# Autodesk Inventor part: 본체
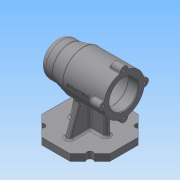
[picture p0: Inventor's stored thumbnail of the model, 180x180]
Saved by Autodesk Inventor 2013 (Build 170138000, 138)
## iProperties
Created: 2021-01
Part Number: 본체
Material: Generic
Document SubType Name: Modeling
Designer: Administrator
Density: 1 g/cm^3
Author: Administrator
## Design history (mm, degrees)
sketch "스케치1" dims "d0" = 100
  geometry: L1 (20.711, 50)-(50, 20.711); L2 (50, 20.711)-(50, -20.711); L3 (50, -20.711)-(20.711, -50); L4 (20.711, -50)-(-20.711, -50); L5 (-20.711, -50)-(-50, -20.711); L6 (-50, -20.711)-(-50, 20.711); L7 (-50, 20.711)-(-20.711, 50); L8 (-20.711, 50)-(20.711, 50); 4 further points
  constraints: 16 end point, 2 coincident, 2 vertical alignment, 1 midpoint, 19 other
extrude "돌출1" new body sketch "스케치1" distance "d2" = 10; taper "d3" = 0 deg
sketch "스케치2"
  geometry: L1 (-50, -10)-(-20.711, -10) reference; L2 (20.711, 0)-(50, 0) reference; L3 (50, 65)-(-50, 65); L4 (-50, 65)-(-50, 90); L5 (-50, 90)-(-30, 90); L6 (-30, 90)-(-10, 95); L7 (-10, 95)-(50, 95); L8 (50, 95)-(50, 86); L9 (50, 86)-(35, 86); L10 (35, 86)-(35, 89); L11 (35, 89)-(-7, 89); L12 (-7, 89)-(-7, 86); L13 (-7, 86)-(-19, 86); L14 (-19, 86)-(-19, 82.5); L15 (-19, 82.5)-(-37, 82.5); L16 (-37, 82.5)-(-37, 81); L17 (-37, 81)-(-41, 81); L18 (-41, 81)-(-41, 75.5); L19 (-41, 75.5)-(-44, 75.5); L20 (-44, 75.5)-(-44, 65); 1 further point
  constraints: 36 end point, 14 parallel, 3 perpendicular, 1 point on line, 1 vertical alignment
  dimensions: "d5" = 75 distance between parallel lines of L3 L1; "d6" = 100 distance of L3.start L3.end; "d8" = 21 diameter of L19 L3; "d9" = 32 diameter of L17 L3; "d10" = 35 diameter of L15 L3; "d11" = 42 diameter of L13 L3; "d12" = 48 diameter of L11 L3; "d13" = 42 diameter of L9 L3; "d14" = 60 diameter of L7 L3; "d15" = 50 diameter of L5 L3; "d16" = 3 distance of L18.end L19.end; "d17" = 4 distance of L16.end L17.end; "d18" = 18 distance of L14.end L15.end; "d19" = 12 distance of L12.end L13.end; "d20" = 42 distance of L10.end L11.end; "d21" = 15 distance of L8.end L9.end; "d22" = 20 distance of L5.end L4.end; "d23" = 40 horizontal distance of L6.end L4.end; "d24" = 100 distance between parallel lines of L8 L4
revolve "회전1" sketch "스케치2" stored, may be unused: angle "d25" = 90 deg
sketch "스케치3"
  geometry: L1 (-20.711, 0)-(20.711, 0) reference; L2 (-50, 0)-(-20.711, 0) reference; L3 (20.711, 0)-(50, 0) reference; L4 (-50, 40)-(-30, 40) reference; L5 (-30, 40)-(-10, 35) reference; L6 (-10, 35)-(50, 35) reference; L7 (-27, 0)-(-19.225, 40); L8 (27, 35)-(27, 0); L9 (-19.225, 40)-(27, 40); L10 (27, 40)-(27, 35); 1 further point
  constraints: 8 end point, 4 point on line, 3 perpendicular
  dimensions: "d26" = 23 distance of L7.start L2.start; "d27" = 101 deg angle of L7 L2; "d28" = 23 distance of L3.end L8.end
extrude "돌출2" join sketch "스케치3" stored distance "d29" = 8; taper "d30" = 0 deg
sketch "스케치4"
  geometry: L1 (-50, 0)-(-20.711, 0) reference; L2 (-20.711, 0)-(-20.711, -10) reference; L3 (-50, -10)-(-20.711, -10) reference; L4 (-50, 0)-(-50, -10) reference; L5 (20.711, 0)-(50, 0) reference; L6 (-35, 0)-(-19.606, 42.293); L7 (19.606, 42.293)-(35, 0); A1 r 30 centre (0, 65) between (4, 35.268) and (-4, 35.268) reference; 1 further point
  constraints: 4 end point, 2 point on circle, 2 point on line
  dimensions: "d31" = 15 distance of L6.start L1.start; "d32" = 15 distance of L5.end L7.end; "d33" = 110 deg angle of L6 L1; "d34" = 110 deg angle of L5 L7
  node "투영된 루프1"
feature "리브1" dims "d35" = 1, "d36" = 8, "d37" = 0, "d38" = 0, "d39" = 1, "d40" = 1
feature "리브2" dims "d41" = 1, "d42" = 8, "d43" = 0, "d44" = 0, "d45" = 1, "d46" = 1
sketch "스케치5"
  geometry: C1 r 21 at (0, 0) reference; C2 r 6 at (0, -30); C3 r 6 at (30, 0); C4 r 6 at (0, 30); C5 r 6 at (-30, 0); A1 r 30 centre (0, 0) between (0, -30) and (30, 0) reference; 1 further point
  constraints: 4 centre point, 4 point on circle, 3 equal radius, 2 horizontal alignment, 2 vertical alignment
  dimensions: "d47" = 12 diameter of C2
extrude "돌출3" join sketch "스케치5" distance "d49" = 16; taper "d50" = 0 deg
sketch "스케치6"
  geometry: A1 r 6 centre (0, 0) between (-5.97, 0.6) and (5.97, 0.6) reference; A2 r 6 centre (30, 30) between (29.4, 24.03) and (29.4, 35.97) reference; A3 r 6 centre (0, 60) between (5.97, 59.4) and (-5.97, 59.4) reference; A4 r 6 centre (-30, 30) between (-29.4, 35.97) and (-29.4, 24.03) reference; 5 further points
  constraints: 4 coincident
hole "구멍1" sketch "스케치6" at (0, 60), (-30, 30), (0, 0), (30, 30) diameter "d51" = 3.242; stored, may be unused: countersink angle "d55" = 90 deg, drill point angle "d57" = 118 deg; dims "d52" = 8, "d53" = 4, "d54" = 2, "d56" = 10
sketch "스케치7"
  geometry: L1 (20.711, 50)-(50, 20.711) reference; L2 (-50, 20.711)-(-20.711, 50) reference; L3 (-20.711, -50)-(-50, -20.711) reference; L4 (50, -20.711)-(20.711, -50) reference; L5 (0, 0)-(-35.355, 35.355); L6 (0, 0)-(-35.355, -35.355); L7 (0, 0)-(35.355, -35.355); L8 (0, 0)-(35.355, 35.355); C1 r 4.5 at (-35.355, 35.355); C2 r 4.5 at (-35.355, -35.355); C3 r 4.5 at (35.355, -35.355); C4 r 4.5 at (35.355, 35.355)
  constraints: 8 end point, 4 centre point, 4 coincident, 4 midpoint, 3 equal radius
  dimensions: "d59" = 9 diameter of C1
extrude "돌출4" cut sketch "스케치7" distance "d61" = 10; taper "d62" = 0 deg
node "작업 평면1"
sketch "스케치8"
  geometry: L1 (50, 70.97)-(50, 94.4) reference; L2 (-50, 40)-(-50, 90) reference; 3 further points
  constraints: 1 horizontal alignment, 1 midpoint, 1 other
  dimensions: "d64" = 38 distance from line of L1 point (12, 65)
feature "엠보싱1" sketch "스케치8" dims "d5" = 75, "d6" = 100, "d8" = 21, "d9" = 32, "d10" = 35, "d11" = 42, "d12" = 48, "d13" = 42, "d14" = 60, "d15" = 50, "d16" = 3, "d17" = 4, "d18" = 18, "d19" = 12, "d20" = 42, "d21" = 15, "d22" = 20, "d23" = 40, "d24" = 100, "d65" = 0.5, "d66" = 0
fillet "모깎기1" dims "d67" = 10
fillet "모깎기2" dims "d68" = 3
fillet "모깎기3" dims "d69" = 1
fillet "모깎기4" dims "d70" = 0.3
fillet "모깎기5" dims "d71" = 3
fillet "모깎기6" dims "d72" = 3
chamfer "모따기1" distance "d73" = 1; stored, may be unused: second distance "d74" = 2, angle "d75" = 45 deg
fillet "모깎기7" dims "d76" = 3
fillet "모깎기8" dims "d77" = 3
fillet "모깎기9" dims "d78" = 3
fillet "모깎기10" dims "d79" = 3
fillet "모깎기11" dims "d80" = 3
node "솔리드1"
